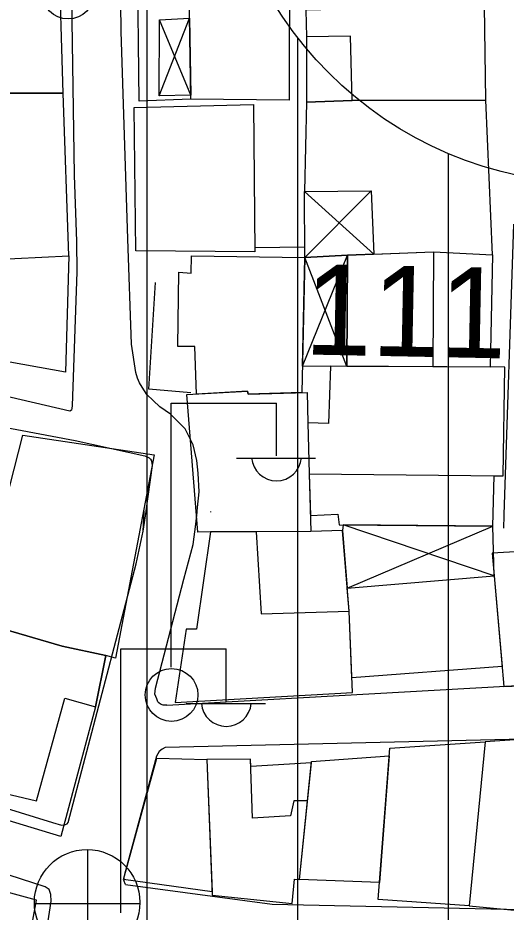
# Model space of a CAD drawing. Extents: x 417997 to 421451, y 4451742 to 4455216.
# Drawn here: x 419576.4 to 419608.7, y 4453017.9 to 4453077.2 of the extents above; entities that cross this region are included whole.
import ezdxf

# ---------------------------------------------------------------- set-up
doc = ezdxf.new("R2010")
doc.units = 0
for name, color, linetype in [('B_Mesken', 7, 'Continuous'), ('B_Sundurma', 7, 'Continuous'), ('B_Teras', 7, 'Continuous'), ('S_Elektrik_Diregi', 7, 'Continuous'), ('S_Rogar_Kapagi', 7, 'Continuous'), ('Sinir_Duvar_tek_tarafa_ait', 7, 'Continuous'), ('SM_DAIRE', 7, 'Continuous'), ('TR_ORTAYOGUNKONUT', 7, 'Continuous'), ('Y_Yol_Kotu', 7, 'Continuous'), ('Yol_Sose', 7, 'Continuous')]:
    doc.layers.add(name, color=color, linetype=linetype)

msp = doc.modelspace()

# ---------------------------------------------------------------- linework, layer by layer
at = {"layer": 'B_Mesken'}
for points in [[(419579.369, 4453072.178), (419579.071, 4453081.82), (419569.473, 4453081.297), (419567.321, 4453081.19), (419567.572, 4453071.881), (419570.564, 4453072.023), (419570.567, 4453072.186)], [(419587.845, 4453071.769), (419584.414, 4453071.638), (419584.291, 4453081.346), (419587.689, 4453081.393), (419594.389, 4453081.407), (419594.368, 4453071.712)], [(419607.391, 4453071.709), (419607.308, 4453077.963), (419607.581, 4453077.97), (419607.756, 4453081.31), (419597.447, 4453081.061), (419597.447, 4453077.724), (419595.458, 4453077.669), (419595.51, 4453075.912), (419595.502, 4453071.572), (419598.526, 4453071.694)], [(419579.744, 4453061.395), (419579.369, 4453072.178), (419570.567, 4453072.186), (419570.382, 4453061.088), (419572.55, 4453061.033)], [(419592.085, 4453061.651), (419584.19, 4453061.728), (419584.077, 4453071.225), (419592, 4453071.425)], [(419607.847, 4453061.456), (419607.391, 4453071.709), (419598.526, 4453071.694), (419595.502, 4453071.572), (419595.374, 4453065.649), (419599.789, 4453065.698), (419599.977, 4453061.514), (419603.94, 4453061.656)], [(419572.55, 4453061.033), (419579.744, 4453061.395), (419579.528, 4453053.696), (419569.527, 4453055.477), (419567.373, 4453055.827), (419567.665, 4453061.157)], [(419588.219, 4453052.239), (419588.108, 4453055.39), (419586.963, 4453055.378), (419587.031, 4453060.319), (419587.848, 4453060.253), (419587.885, 4453061.393), (419595.407, 4453061.292), (419595.192, 4453052.33), (419591.649, 4453052.23), (419591.597, 4453052.421)], [(419603.94, 4453061.656), (419607.847, 4453061.456), (419607.693, 4453054.019), (419603.896, 4453054.04), (419598.179, 4453054.071), (419598.222, 4453061.451)], [(419607.868, 4453043.481), (419607.951, 4453046.82), (419608.54, 4453046.814), (419608.67, 4453054.013), (419603.896, 4453054.04), (419597.09, 4453054.077), (419596.972, 4453050.296), (419595.6, 4453050.321), (419595.694, 4453046.955), (419595.77, 4453044.184), (419597.596, 4453044.268), (419597.672, 4453043.561)], [(419587.564, 4453052.204), (419591.597, 4453052.421), (419591.649, 4453052.23), (419595.545, 4453052.34), (419595.6, 4453050.321), (419595.694, 4453046.955), (419595.799, 4453043.128), (419588.309, 4453043.094)], [(419573.543, 4453037.21), (419576.688, 4453049.518), (419585.405, 4453048.208), (419582.848, 4453034.728), (419582.193, 4453034.9), (419579.304, 4453035.535)], [(419598.558, 4453032.462), (419598.328, 4453037.857), (419597.905, 4453043.196), (419595.799, 4453043.128), (419592.169, 4453043.111), (419589.144, 4453043.098), (419588.201, 4453036.662), (419587.521, 4453036.657), (419586.792, 4453031.79)], [(419618.084, 4453042.282), (419607.822, 4453041.693), (419608.594, 4453032.865), (419618.107, 4453033.235)], [(419598.328, 4453037.857), (419598.208, 4453039.378), (419607.954, 4453040.183), (419608.479, 4453034.176), (419598.516, 4453033.437)], [(419579.215, 4453022.907), (419570.534, 4453025.538), (419570.645, 4453025.835), (419570.871, 4453026.86), (419571.582, 4453029.995), (419571.839, 4453029.954), (419572.772, 4453034.513), (419573.543, 4453037.21), (419579.304, 4453035.535), (419582.193, 4453034.9), (419581.513, 4453031.512)], [(419607.35, 4453029.189), (419606.303, 4453018.312), (419609.998, 4453017.974), (419610.941, 4453029.44)], [(419606.303, 4453018.312), (419600.271, 4453018.744), (419601.028, 4453028.778), (419607.35, 4453029.189)], [(419589.244, 4453019.246), (419583.367, 4453020.072), (419585.585, 4453028.116), (419588.89, 4453028.015)], [(419600.356, 4453019.872), (419595.032, 4453020.061), (419595.842, 4453027.895), (419600.988, 4453028.251)], [(419591.811, 4453027.558), (419591.794, 4453028.04), (419588.89, 4453028.015), (419589.252, 4453019.034), (419594.56, 4453018.468), (419594.716, 4453020.08), (419595.032, 4453020.061), (419595.833, 4453027.803)], [(419564.442, 4453022.273), (419563.414, 4453015.71), (419565.201, 4453015.272), (419576.498, 4453012.674), (419577.59, 4453018.692)]]:
    msp.add_lwpolyline(points, close=True, dxfattribs=at)
at = {"layer": 'B_Sundurma'}
for p, q in [((419585.73, 4453072.004), (419587.758, 4453077.157)), ((419587.841, 4453072.051), (419585.75, 4453077.036)), ((419595.374, 4453065.649), (419599.977, 4453061.514)), ((419595.407, 4453061.292), (419599.789, 4453065.698)), ((419595.234, 4453054.087), (419598.222, 4453061.451)), ((419598.179, 4453054.071), (419595.407, 4453061.292)), ((419607.954, 4453040.183), (419597.943, 4453043.559)), ((419598.208, 4453039.378), (419607.868, 4453043.481))]:
    msp.add_line(p, q, dxfattribs=at)
for points in [[(419587.841, 4453072.051), (419585.73, 4453072.004), (419585.75, 4453077.036), (419587.758, 4453077.157)], [(419598.222, 4453061.451), (419595.407, 4453061.292), (419595.374, 4453065.649), (419599.789, 4453065.698), (419599.977, 4453061.514)], [(419598.179, 4453054.071), (419595.234, 4453054.087), (419595.407, 4453061.292), (419598.222, 4453061.451)], [(419597.905, 4453043.196), (419598.208, 4453039.378), (419607.954, 4453040.183), (419607.868, 4453043.481), (419597.943, 4453043.559)]]:
    msp.add_lwpolyline(points, close=True, dxfattribs=at)
at = {"layer": 'B_Teras'}
for points in [[(419587.845, 4453071.769), (419587.689, 4453081.393), (419594.389, 4453081.407), (419594.368, 4453071.712)], [(419595.51, 4453075.912), (419595.502, 4453071.572), (419598.526, 4453071.694), (419598.424, 4453075.954)], [(419603.896, 4453054.04), (419598.179, 4453054.071), (419598.222, 4453061.451), (419603.94, 4453061.656)], [(419595.694, 4453046.955), (419608.54, 4453046.814), (419608.67, 4453054.013), (419597.09, 4453054.077), (419596.972, 4453050.296), (419595.6, 4453050.321)], [(419592.169, 4453043.111), (419592.508, 4453037.666), (419598.328, 4453037.857), (419597.905, 4453043.196), (419595.799, 4453043.128)], [(419572.772, 4453034.513), (419571.839, 4453029.954), (419571.582, 4453029.995), (419570.85, 4453026.865), (419577.59, 4453025.271), (419579.48, 4453032.094), (419581.513, 4453031.512), (419582.193, 4453034.9), (419579.304, 4453035.535), (419573.543, 4453037.21)], [(419588.89, 4453028.015), (419589.252, 4453019.034), (419594.56, 4453018.468), (419594.716, 4453020.08), (419595.032, 4453020.061), (419595.571, 4453025.276), (419594.666, 4453025.277), (419594.436, 4453024.283), (419591.932, 4453024.122), (419591.794, 4453028.04)]]:
    msp.add_lwpolyline(points, close=True, dxfattribs=at)
at = {"layer": 'S_Elektrik_Diregi'}
for p, q in [((419586.522, 4453034.132), (419586.522, 4453051.632)), ((419586.522, 4453051.632), (419593.522, 4453051.632)), ((419593.522, 4453048.132), (419593.522, 4453051.632)), ((419590.862, 4453047.992), (419596.112, 4453047.992)), ((419583.187, 4453017.86), (419583.187, 4453035.36)), ((419583.187, 4453035.36), (419590.187, 4453035.36)), ((419590.187, 4453031.86), (419590.187, 4453035.36)), ((419587.527, 4453031.72), (419592.777, 4453031.72))]:
    msp.add_line(p, q, dxfattribs=at)
for centre in [(419579.697, 4453078.848), (419586.558, 4453032.296)]:
    msp.add_circle(centre, 1.75, dxfattribs=at)
for centre in [(419593.522, 4453048.145), (419590.187, 4453031.873)]:
    msp.add_arc(centre, 1.658, 184.83843, 355.14641, dxfattribs=at)
at = {"layer": 'S_Rogar_Kapagi'}
for p, q in [((419581.01, 4453015.02), (419581.01, 4453022.02)), ((419577.44, 4453018.485), (419584.44, 4453018.485))]:
    msp.add_line(p, q, dxfattribs=at)
msp.add_circle((419580.957, 4453018.549), 3.5, dxfattribs=at)
at = {"layer": 'Sinir_Duvar_tek_tarafa_ait'}
for points in [[(419595.402, 4453061.974), (419592.082, 4453061.927)], [(419587.826, 4453052.328), (419585.061, 4453052.571), (419585.486, 4453059.624)]]:
    msp.add_lwpolyline(points, dxfattribs=at)
at = {"layer": 'SM_DAIRE'}
msp.add_circle((419614.657, 4453091.193), 25, dxfattribs=at)
msp.add_circle((419614.657, 4453091.193), 25, dxfattribs=at)
at = {"layer": 'TR_ORTAYOGUNKONUT'}
for p, q in [((419584.929, 4452960.268), (419584.929, 4453191.697)), ((419584.929, 4452960.268), (419584.929, 4453191.697)), ((419594.929, 4452962.693), (419594.929, 4453075.837)), ((419594.929, 4452962.693), (419594.929, 4453075.837)), ((419604.929, 4452965.119), (419604.929, 4453068.164)), ((419604.929, 4452965.119), (419604.929, 4453068.164))]:
    msp.add_line(p, q, dxfattribs=at)
at = {"layer": 'Yol_Sose'}
for points in [[(419547.559, 4453066.536), (419552.538, 4453084.727), (419558.753, 4453110.438), (419558.905, 4453110.797), (419559.235, 4453111.025), (419578.415, 4453110.698), (419578.592, 4453110.652), (419578.727, 4453110.594), (419578.894, 4453110.506), (419579.051, 4453110.383), (419579.167, 4453110.271), (419579.391, 4453110.019), (419579.507, 4453109.802), (419579.527, 4453109.71), (419579.774, 4453101.874), (419579.859, 4453082.823), (419580.107, 4453066.744), (419580.253, 4453062.343), (419580.286, 4453060.342)], [(419588.251, 4453044.452), (419588.275, 4453044.719), (419588.38, 4453045.751), (419588.321, 4453046.988), (419588.225, 4453047.831), (419587.992, 4453048.871), (419587.468, 4453049.931), (419586.48, 4453050.911), (419585.782, 4453051.397), (419585.348, 4453051.81), (419584.927, 4453052.215), (419584.602, 4453052.69), (419584.423, 4453052.988), (419584.308, 4453053.295), (419584.184, 4453053.673), (419583.895, 4453055.54), (419583.653, 4453062.518), (419583.207, 4453076.262), (419583.006, 4453093.231)], [(419580.286, 4453060.342), (419579.964, 4453051.455), (419579.953, 4453051.306), (419579.912, 4453051.179), (419579.813, 4453051.113), (419565.558, 4453054.417), (419554.027, 4453057.733), (419546.425, 4453059.864), (419546.323, 4453059.94), (419546.263, 4453060.021), (419546.193, 4453060.155), (419546.129, 4453060.323), (419546.127, 4453060.348), (419546.13, 4453060.473), (419547.559, 4453066.536)], [(419608.627, 4453044.237), (419609.248, 4453063.496)], [(419545.153, 4453057.055), (419545.211, 4453057.138), (419545.338, 4453057.21), (419545.481, 4453057.211), (419545.522, 4453057.208), (419553.518, 4453055.124), (419565.725, 4453051.871), (419580.174, 4453049.15), (419584.791, 4453048.149), (419585.069, 4453048.008), (419585.157, 4453047.929), (419585.222, 4453047.816), (419585.228, 4453047.767), (419585.252, 4453047.664), (419585.274, 4453047.502), (419584.85, 4453044.488)], [(419542.699, 4453044.895), (419541.037, 4453036.657), (419541.051, 4453036.294), (419541.051, 4453036.218), (419541.096, 4453036.112), (419541.186, 4453035.975), (419541.262, 4453035.899), (419541.791, 4453035.581), (419554.77, 4453031.213), (419578.654, 4453023.843), (419579.26, 4453023.676), (419579.533, 4453023.705), (419579.639, 4453023.766), (419579.7, 4453023.842), (419584.202, 4453040.99), (419584.664, 4453043.157), (419584.732, 4453044.446)], [(419584.844, 4453044.445), (419584.661, 4453043.145)], [(419584.732, 4453044.446), (419584.734, 4453044.489)], [(419584.85, 4453044.488), (419584.844, 4453044.445)], [(419586.255, 4453031.609), (419585.999, 4453031.626), (419585.83, 4453031.687), (419585.718, 4453031.764), (419585.654, 4453031.831), (419585.58, 4453032.045), (419585.456, 4453032.339), (419585.487, 4453032.748), (419587.381, 4453039.979), (419587.998, 4453042.264), (419588.178, 4453043.625), (419588.247, 4453044.409)], [(419588.247, 4453044.409), (419588.251, 4453044.452)], [(419589.136, 4453044.443), (419589.144, 4453044.399)], [(419608.599, 4453043.354), (419608.626, 4453044.192)], [(419608.626, 4453044.192), (419608.627, 4453044.237)], [(419586.255, 4453031.609), (419617.767, 4453033.393), (419634.188, 4453033.972), (419635.342, 4453034.304), (419636.073, 4453035.061), (419636.677, 4453043.892)], [(419534.544, 4453001.367), (419554.274, 4452995.219), (419573.164, 4452990.474), (419573.695, 4452990.428), (419574.059, 4452990.518), (419574.211, 4452990.609), (419574.333, 4452990.866), (419578.567, 4453018.625), (419578.553, 4453019.08), (419578.433, 4453019.398), (419578.176, 4453019.58), (419540.781, 4453031.695), (419540.554, 4453031.68), (419540.341, 4453031.559), (419540.341, 4453031.559), (419534.253, 4453002.16), (419534.268, 4453001.918), (419534.312, 4453001.676)], [(419583.492, 4453019.744), (419593.238, 4453018.439), (419617.058, 4453017.914), (419634.289, 4453019.264), (419635.293, 4453019.869), (419635.537, 4453020.232), (419635.753, 4453021.202), (419635.443, 4453028.42), (419635.292, 4453028.739), (419635.035, 4453029.058), (419634.929, 4453029.104), (419634.019, 4453029.469), (419611.81, 4453029.4), (419586.139, 4453028.82), (419585.927, 4453028.699), (419585.729, 4453028.548), (419585.561, 4453028.245), (419583.441, 4453020.397), (419583.395, 4453020.2), (419583.394, 4453020.003)], [(419583.492, 4453019.744), (419583.394, 4453020.003)]]:
    msp.add_lwpolyline(points, dxfattribs=at)

# ---------------------------------------------------------------- texts
at = {"layer": 'Y_Yol_Kotu'}
msp.add_text('111.04 ', height=6, rotation=358.87031, dxfattribs=at).set_placement((419595.332, 4453054.861))

doc.saveas('drawing.dxf')
